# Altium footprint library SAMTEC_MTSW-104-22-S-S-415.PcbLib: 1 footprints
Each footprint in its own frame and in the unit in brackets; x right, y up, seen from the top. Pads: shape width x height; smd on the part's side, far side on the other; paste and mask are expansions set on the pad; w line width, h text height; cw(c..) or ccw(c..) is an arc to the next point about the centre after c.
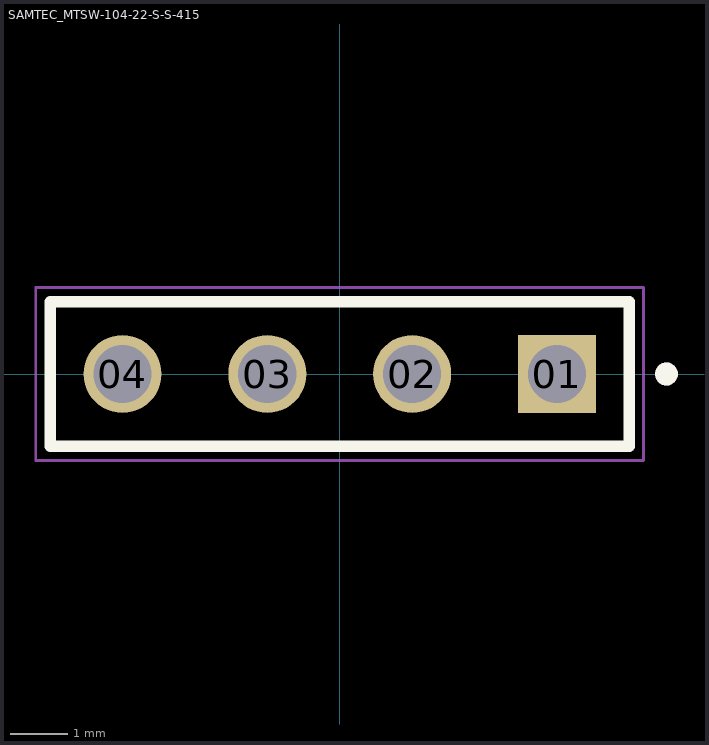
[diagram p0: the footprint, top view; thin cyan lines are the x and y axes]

## SAMTEC_MTSW-104-22-S-S-415 [mm]
pads (4):
  rect 1.37x1.37 / inner round 1.37 / far side rect 1.37x1.37 hole 1.02: 01(3.81,0)
  round 1.37 hole 1.02: 02(1.27,0) 03(-1.27,0) 04(-3.81,0)
Top Overlay:
  circle w0.2: c5.73,0 r0.1
  lines w0.2: -5.08,-1.27 -5.08,1.27 5.08,1.27 5.08,-1.27 -5.08,-1.27
Mechanical 13:
  circle w0.2: c5.73,0 r0.1
  lines w0.1: -5.08,-1.27 -5.08,1.27 ; -5.08,-1.27 5.08,-1.27 ; -5.08,-1.27 -5.08,1.27 ; -5.08,1.27 5.08,1.27 ; -5.08,1.27 5.08,1.27 ; 5.08,-1.27 5.08,1.27 ; 5.08,-1.27 5.08,1.27
Mechanical 15:
  lines w0.05: -5.33,-1.52 -5.33,1.52 5.33,1.52 5.33,-1.52 -5.33,-1.52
